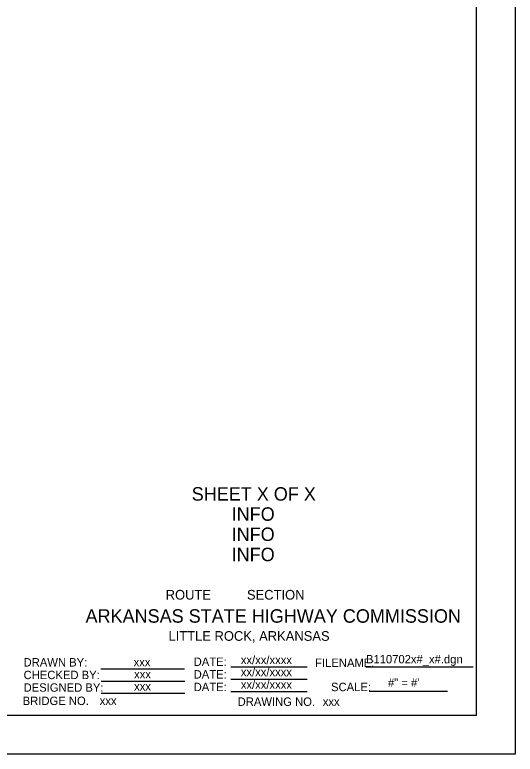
# Model space of a CAD drawing. Extents: x 16 to 1228740, y 11 to 152440.
# Drawn here: x 17.87 to 18.49, y 10.709 to 11.626 of the extents above; entities that cross this region are included whole.
import ezdxf

# ---------------------------------------------------------------- set-up
doc = ezdxf.new("R2010")
doc.units = 0
for name, color, linetype in [('B_Copy In', 7, 'Continuous'), ('B_Text', 7, 'Continuous'), ('B_Title Text', 7, 'Continuous'), ('R_Border', 7, 'Continuous')]:
    doc.layers.add(name, color=color, linetype=linetype)

msp = doc.modelspace()

# ---------------------------------------------------------------- linework, layer by layer
at = {"layer": 'B_Text'}
for p, q in [((18.13771, 10.81765), (18.23221, 10.81765)), ((18.30529, 10.81765), (18.43835, 10.81765)), ((17.97661, 10.81515), (18.08021, 10.81515)), ((17.97721, 10.80015), (18.08081, 10.80015)), ((18.13771, 10.80265), (18.23221, 10.80265)), ((18.13771, 10.80265), (18.23221, 10.80265)), ((17.97721, 10.78515), (18.08081, 10.78515)), ((18.13771, 10.78703), (18.23221, 10.78703)), ((18.30917, 10.78765), (18.40631, 10.78765))]:
    msp.add_line(p, q, dxfattribs=at)
at = {"layer": 'R_Border'}
for q in [(18.44221, 12.49475), (15.78327, 10.75755)]:
    msp.add_line((18.44221, 10.75755), q, dxfattribs=at)
msp.add_lwpolyline([(15.65694, 12.54282), (18.49027, 12.54282), (18.49027, 10.70949), (15.65694, 10.70949)], close=True, dxfattribs=at)

# ---------------------------------------------------------------- texts
at = {"layer": 'B_Copy In'}
for s, height, p in [('SHEET X OF X', 0.0167, (18.08929, 11.02383)), ('INFO', 0.0167, (18.13883, 10.99888)), ('INFO', 0.0167, (18.13883, 10.97383)), ('INFO', 0.0167, (18.13883, 10.94878)), ('xxx', 0.0104, (18.0173, 10.81846)), ('xx/xx/xxxx', 0.0104, (18.15019, 10.82119)), ('B110702x#_x#.dgn', 0.0104, (18.30529, 10.8221)), ('xx/xx/xxxx', 0.0104, (18.15019, 10.80619)), ('xxx', 0.0104, (18.0179, 10.80346)), ('xx/xx/xxxx', 0.0104, (18.15019, 10.79057)), ('#" = #\'', 0.0104, (18.33262, 10.79302)), ('xxx', 0.0104, (18.0179, 10.78846)), ('xxx', 0.010417, (17.97523, 10.7706)), ('xxx', 0.010417, (18.25173, 10.76944))]:
    msp.add_text(s, height=height, dxfattribs=at).set_placement(p)
at = {"layer": 'B_Text'}
for s, height, p in [('DRAWN BY:', 0.010417, (17.88091, 10.8182)), ('DATE:', 0.010417, (18.09171, 10.8189)), ('FILENAME:', 0.010417, (18.24229, 10.81765)), ('CHECKED BY:', 0.0104166, (17.88091, 10.80257)), ('DATE:', 0.010417, (18.09171, 10.80328)), ('DESIGNED BY:', 0.0104166, (17.88091, 10.78695)), ('DATE:', 0.010417, (18.09171, 10.78765)), ('SCALE:', 0.010417, (18.26201, 10.78765)), ('BRIDGE NO.', 0.010417, (17.87978, 10.77048)), ('DRAWING NO.', 0.0104166, (18.14623, 10.76942))]:
    msp.add_text(s, height=height, dxfattribs=at).set_placement(p)
at = {"layer": 'B_Title Text'}
for s, height, p in [('ROUTE          SECTION ', 0.012, (18.05705, 10.90115)), ('ARKANSAS STATE HIGHWAY COMMISSION', 0.0167, (17.95772, 10.8725)), ('LITTLE ROCK, ARKANSAS', 0.012, (18.0605, 10.85007))]:
    msp.add_text(s, height=height, dxfattribs=at).set_placement(p)

doc.saveas('drawing.dxf')
